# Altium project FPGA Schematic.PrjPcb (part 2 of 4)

## Sheet TPSM5D1806 Multi Phase.SchDoc
size A2; Date: Not shown in title block; ApprovedBy: Not shown in title block; CheckedBy: Not shown in title block; Author: Not shown in title block; CompanyName: Not shown in title block; Engineer: Not shown in title block; Organization: Not shown in title block; Address1: Not shown in title block; Address2: Not shown in title block; Address3: Not shown in title block; Address4: Not shown in title block; DocumentNumber: 16; Revision: Use project parameter SCH_Rev; SheetNumber: 16; SheetTotal: 17; PageSetup: Record=PageOptions¦CenterHorizontal=True¦CenterVertical=True¦PrintScale=1.00¦XCorrection=1.00¦YCorrection=1.00¦PrintKind=0¦BorderSize=5000000¦LeftOffset=0¦BottomOffset=0¦Orientation=2¦PaperLength=1000¦PaperWidth=1000¦Scale=100¦PaperSource=15¦PrintQuality=600¦MediaType=1¦DitherType=10¦PaperKind=Letter¦PrintScaleMode=1
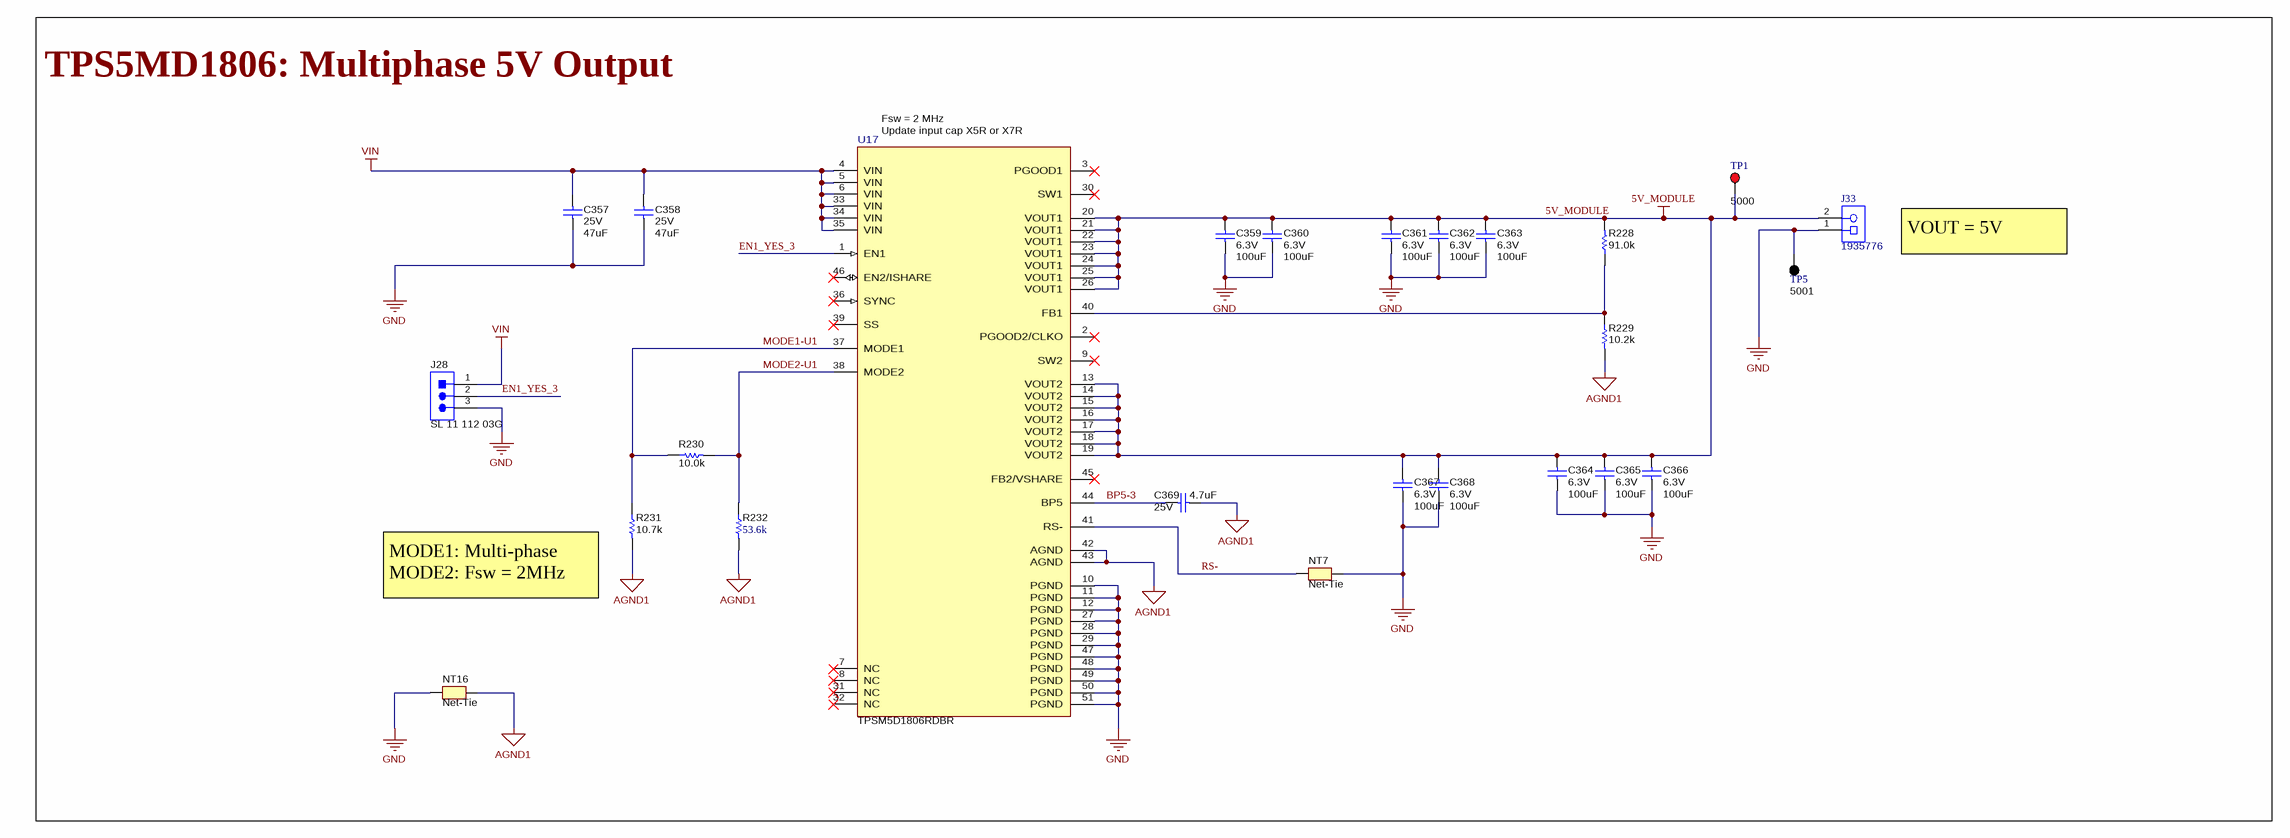
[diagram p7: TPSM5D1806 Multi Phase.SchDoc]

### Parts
C357  VDC_V: 25V  ValueDisplayed: 47uF  [1206_190L]  (hidden comment: CKG57NX5R1E476M500JH)
C358  VDC_V: 25V  ValueDisplayed: 47uF  [1206_190L]  (hidden comment: CKG57NX5R1E476M500JH)
C359  VDC_V: 6.3V  ValueDisplayed: 100uF  [0805L]  (hidden comment: GRM21BR60J107M)
C360  VDC_V: 6.3V  ValueDisplayed: 100uF  [0805L]  (hidden comment: GRM21BR60J107M)
C361  VDC_V: 6.3V  ValueDisplayed: 100uF  [0805L]  (hidden comment: GRM21BR60J107M)
C362  VDC_V: 6.3V  ValueDisplayed: 100uF  [0805L]  (hidden comment: GRM21BR60J107M)
C363  VDC_V: 6.3V  ValueDisplayed: 100uF  [0805L]  (hidden comment: GRM21BR60J107M)
C364  VDC_V: 6.3V  ValueDisplayed: 100uF  [0805L]  (hidden comment: GRM21BR60J107M)
C365  VDC_V: 6.3V  ValueDisplayed: 100uF  [0805L]  (hidden comment: GRM21BR60J107M)
C366  VDC_V: 6.3V  ValueDisplayed: 100uF  [0805L]  (hidden comment: GRM21BR60J107M)
C367  VDC_V: 6.3V  ValueDisplayed: 100uF  [0805L]  (hidden comment: GRM21BR60J107M)
C368  VDC_V: 6.3V  ValueDisplayed: 100uF  [0805L]  (hidden comment: GRM21BR60J107M)
C369  VDC_V: 25V  ValueDisplayed: 4.7uF  [0402]  (hidden comment: GRM155R61E475ME15)
J28  SL 11 112 03G  [Fischer_SL-11-112-03G]
J33  1935776  [Phoenix_1935776]
NT7  Net-Tie  [Net-Tie6milsWide_20milsLong]  (net tie, no BOM)
NT16  Net-Tie  [Net-Tie_10mil]  (net tie, no BOM)
R228  ValueDisplayed: 91.0k  [0201L]  (hidden comment: RC0201FR-0791KL)
R229  ValueDisplayed: 10.2k  [0201L]  (hidden comment: RC0201FR-0710K2L)
R230  ValueDisplayed: 10.0k  [0201L]  (hidden comment: RC0201FR-7D10KL)
R231  ValueDisplayed: 10.7k  [0201L]  (hidden comment: RC0201FR-0710K7L)
R232  ValueDisplayed: 53.6k  [0201L]  (hidden comment: RC0201FR-0753K6L)
TP1  5000  [Keystone5000]
TP5  5001  [Keystone5001]
U17  PartNumber: TPSM5D1806RDBR  [RDB0051A-MFG]  (hidden comment: TPSM5D1806RDB)

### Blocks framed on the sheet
TPS5MD1806: Multiphase 5V Output: C357-C369 J28 J33 NT7 NT16 R228-R232 TP1 TP5 U17

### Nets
5V_MODULE: C359.1 C360.1 C361.1 C362.1 C363.1 C364.1 C365.1 C366.1 C367.1 C368.1 J33.2 R228.2 TP1.1 U17.13(VOUT2) U17.14(VOUT2) U17.15(VOUT2) U17.16(VOUT2) U17.17(VOUT2) U17.18(VOUT2) U17.19(VOUT2) U17.20(VOUT1) U17.21(VOUT1) U17.22(VOUT1) U17.23(VOUT1) U17.24(VOUT1) U17.25(VOUT1) U17.26(VOUT1)
AGND1: C369.2 NT16.2 R229.2 R231.2 R232.2 U17.42(AGND) U17.43(AGND)
GND: C357.2 C358.2 C359.2 C360.2 C361.2 C362.2 C363.2 C364.2 C365.2 C366.2 C367.2 C368.2 J28.3 J33.1 NT7.2 NT16.1 TP5.1 U17.10(PGND) U17.11(PGND) U17.12(PGND) U17.27(PGND) U17.28(PGND) U17.29(PGND) U17.47(PGND) U17.48(PGND) U17.49(PGND) U17.50(PGND) U17.51(PGND)
VIN: C357.1 C358.1 J28.1 U17.4(VIN) U17.5(VIN) U17.6(VIN) U17.33(VIN) U17.34(VIN) U17.35(VIN)
BP5-3: C369.1 U17.44(BP5)
EN1_YES_3: J28.2 U17.1(EN1)
MODE1-U1: R230.1 R231.1 U17.37(MODE1)
MODE2-U1: R230.2 R232.1 U17.38(MODE2)
RS-: NT7.1 U17.41(RS-)
NetR228_1: R228.1 R229.1 U17.40(FB1)

Not connected (* = marked no-connect by the designer): U17 2(PGOOD2/CLKO)* 3(PGOOD1)* 7(NC)* 8(NC)* 9(SW2)* 30(SW1)* 31(NC)* 32(NC)* 36(SYNC)* 39(SS)* 45(FB2/VSHARE)* 46(EN2/ISHARE)*

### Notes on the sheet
- (near U17) Fsw = 2 MHz
  Update input cap X5R or X7R
- VOUT = 5V
- (near R231) MODE1: Multi-phase
  MODE2: Fsw = 2MHz

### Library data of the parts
C357 C358 = CMP-0008656-2: CAP, CERM, 47 uF, 25 V, +/- 20%, X5R, 1206_190; Manufacturer: TDK; PartNumber: C3216X5R1E476M160AC; TaMin_C: -55°C; Polarized: N; SizeAreaWB_mm2: 10.92; Value1: Unknown; U/M: EA; Value: 47uF; TaMax_C: 85°C; SizeZ_mm: 1.9; SizeX_mm: 3.2; SizeY_mm: 1.6; Cap_Case: 1206; SizeArea_mm2: 5.12; Cap_F: 47µF; AEC Category: Q200
C359-C368 = CMP-0008280-2: CAP, CERM, 100 uF, 6.3 V, +/- 20%, X5R, 0805; Manufacturer: MuRata; TaMin_C: -55°C; Polarized: N; SizeAreaWB_mm2: 6.75; Value1: Unknown; U/M: EA; Value: 100uF; TaMax_C: 85°C; SizeZ_mm: 1.45; SizeX_mm: 2; SizeY_mm: 1.25; Cap_Case: 0805; SizeArea_mm2: 2.5; Cap_F: 100µF; AEC Category: Q200
C369 = CMP-0006612-2: CAP, CERM, 4.7 uF, 25 V, +/- 20%, X5R, 0402; Manufacturer: MuRata; TaMin_C: -55°C; Polarized: N; SizeAreaWB_mm2: 3; Value1: Unknown; U/M: EA; Value: 4.7uF; TaMax_C: 85°C; SizeZ_mm: 0.6; SizeX_mm: 1; SizeY_mm: 0.5; Cap_F: 4.7µF; AEC Category: Q200
J28 = CMP-0075048-1: Header, 2.54mm, 3x1, Gold, TH; Manufacturer: Fischer Elektronik; CT: False; CNHeader: True
J33 = CMP-0055506-1: Terminal Block, 2x1, 5mm, Green, TH; Manufacturer: Phoenix Contact; Pitch_mm: 5; Gender: Female; Row_Count: 1; CNHeader: FALSE; Green_Lifecycle: Not Set; Green_REACh: Incomplete; CT: TRUE
NT7 NT16 = CMP-0078142-4: Single point connection between nets.
R228 = CMP-0027922-1: RES, 91.0 k, 1%, 0.05 W, 0201; Manufacturer: Yageo America; Power_W: 50mW; TempCo: 200 ppm/C; Value_Code: 91k0; U/M: EA; Value: 91.0k; Res_ohm: 91k; SizeX_mm: 0.6; SizeY_mm: 0.3; SizeZ_mm: 0.26; Value2: 0.05W; SizeArea_mm2: 0.18; AEC Qualified: N; VDC_V: 25V; AEC Category: Q200
R229 = CMP-0027301-2: RES, 10.2 k, 1%, 0.05 W, 0201; Manufacturer: Yageo America; Power_W: 50mW; TempCo: 200 ppm/C; Value_Code: 10k2; Value: 10.2k; EIA_Code: E96; SizeX_mm: 0.6; SizeY_mm: 0.3; SizeZ_mm: 0.26; Value2: 0.05W; SizeArea_mm2: 0.18; AEC Qualified: N; VDC_V: 25V; AEC Category: Q200; U/M: EA
R230 = CMP-0027945-1: RES, 10.0 k, 1%, 0.05 W, 0201; Manufacturer: Yageo America; Power_W: 50mW; TempCo: 200 ppm/C; Value_Code: 10k0; U/M: EA; Value: 10.0k; EIA_Code: E96; Res_ohm: 10k; SizeX_mm: 0.6; SizeY_mm: 0.3; SizeZ_mm: 0.26; Value2: 0.05W; SizeArea_mm2: 0.18; AEC Qualified: N; VDC_V: 25V; AEC Category: Q200
R231 = CMP-0027303-2: RES, 10.7 k, 1%, 0.05 W, 0201; Manufacturer: Yageo America; Power_W: 50mW; TempCo: 200 ppm/C; Value_Code: 10k7; U/M: EA; Value: 10.7k; EIA_Code: E96; SizeX_mm: 0.6; SizeY_mm: 0.3; SizeZ_mm: 0.26; Value2: 0.05W; SizeArea_mm2: 0.18; CompType: Resistor; AEC Qualified: N; VDC_V: 25V; AEC Category: Q200
R232 = CMP-0027766-1: RES, 53.6 k, 1%, 0.05 W, 0201; Manufacturer: Yageo America; Power_W: 50mW; TempCo: 200 ppm/C; Value_Code: 53k6; U/M: EA; Value: 53.6k; EIA_Code: E96; SizeX_mm: 0.6; SizeY_mm: 0.3; SizeZ_mm: 0.26; Value2: 0.05W; SizeArea_mm2: 0.18; AEC Qualified: N; VDC_V: 25V; AEC Category: Q200
TP1 = CMP-0055137-1: Test Point, Miniature, Red, TH; Manufacturer: Keystone; ContactFinish: Silver; CNHeader: FALSE; Green_Lifecycle: Active; Green_REACh: Passed; CT: TRUE
TP5 = CMP-0055138-1: Test Point, Miniature, Black, TH; Manufacturer: Keystone; ContactFinish: Silver; CNHeader: FALSE; Green_Lifecycle: Active; Green_REACh: Passed; CT: TRUE
U17 = CMP-0090775-3: 4.5-V to 18-V Input, Dual 6-A / Single 12-A Output Power Module with Current Sharing; Manufacturer: Texas Instruments; AEC Qualified: No; Switching Frequency: 500-1000-1500-2000kHz; Output Voltage: 0.5-5.5V; Output Type: AdjustableProgrammable; TJmax_C: +125°C; Min Supply Voltage: 4.5V; Max Supply Voltage: 18V; Number Of Outputs: 2; Nominal Supply Current: 2.5mA; SizeZ_mm: 1.9mm; Switching Topology: Buck; TaMin_C: -40°C; TaMax_C: +105°C; CompType: IC; AEC Category: Q200

## Sheet EVRHC008_  Filters.SchDoc
size 431 x 279 mm; Date: Not shown in title block; ApprovedBy: Not shown in title block; CheckedBy: Not shown in title block; Author: Not shown in title block; CompanyName: Not shown in title block; Engineer: Not shown in title block; Organization: Not shown in title block; Address1: Not shown in title block; Address2: Not shown in title block; Address3: Not shown in title block; Address4: Not shown in title block; DocumentNumber: 2; Revision: Use project parameter SCH_Rev; SheetNumber: 2; SheetTotal: 17; PageSetup: Record=PageOptions¦CenterHorizontal=True¦CenterVertical=True¦PrintScale=1.00¦XCorrection=1.00¦YCorrection=1.00¦PrintKind=0¦BorderSize=5000000¦LeftOffset=0¦BottomOffset=0¦Orientation=2¦PaperLength=1000¦PaperWidth=1000¦Scale=100¦PaperSource=15¦PrintQuality=600¦MediaType=1¦DitherType=10¦PaperKind=Letter¦PrintScaleMode=1
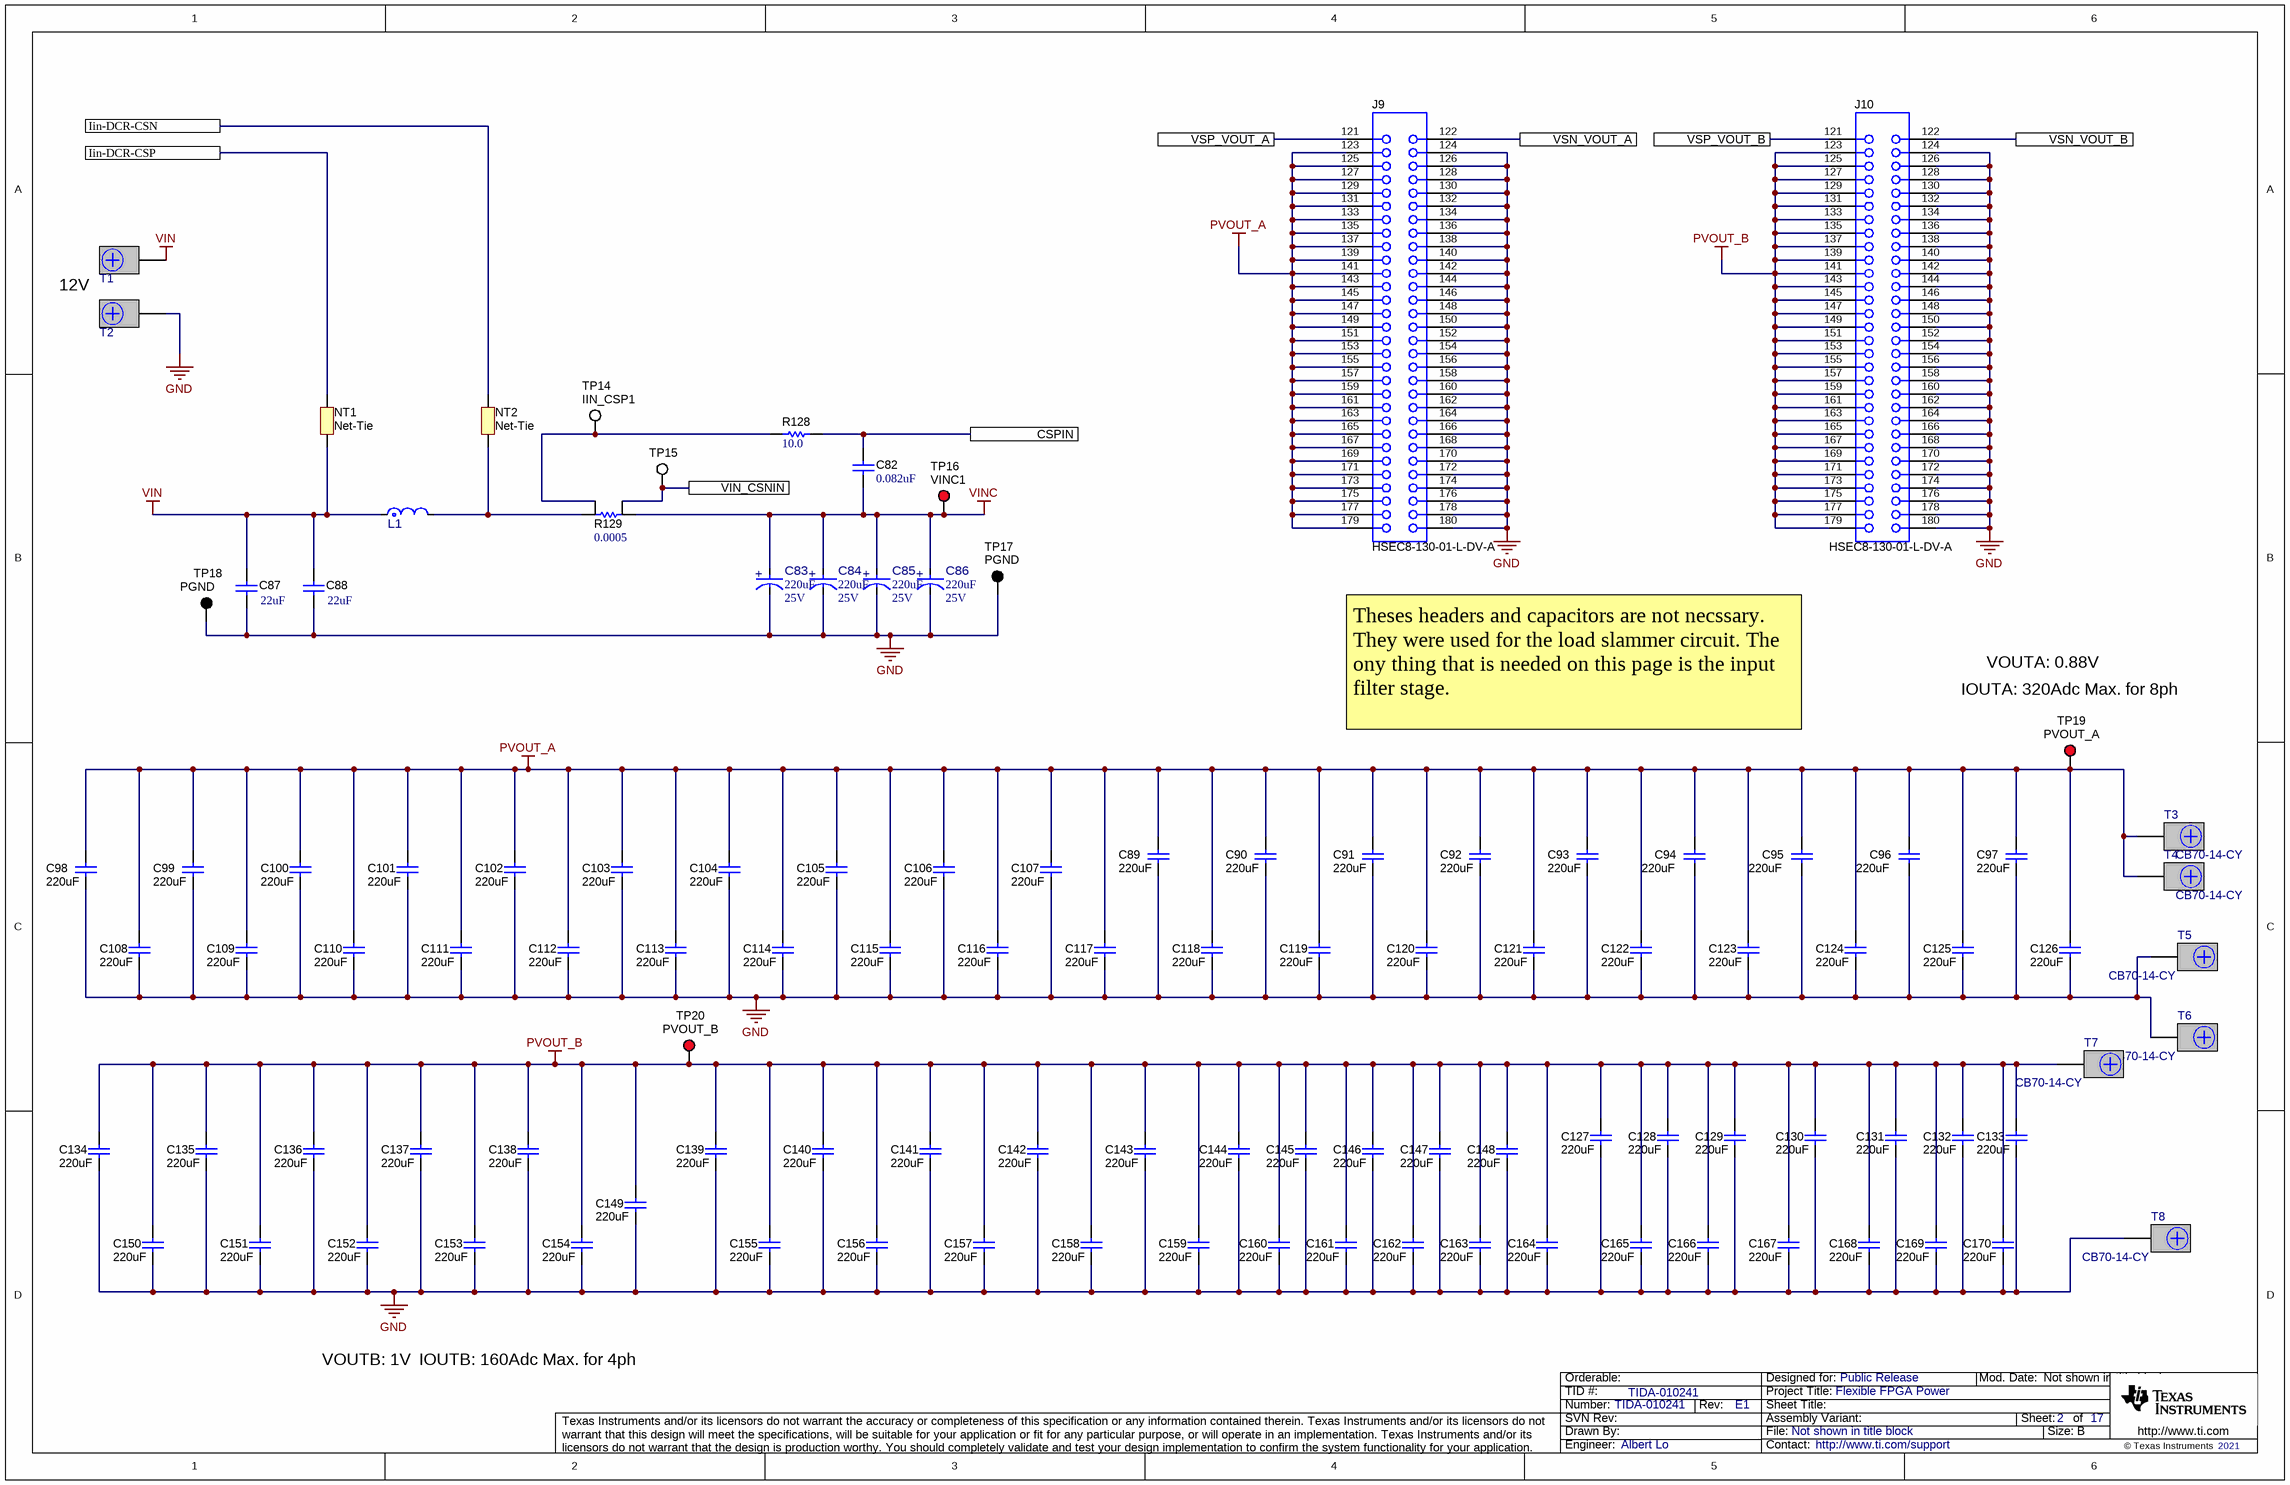
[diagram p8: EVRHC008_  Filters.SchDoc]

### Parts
C82  ValueDisplayed: 0.082uF  [0603S]  (hidden comment: 0603YC823KAT2A)
C83  ValueDisplayed: 220uF  VDC_V: 25V  [FP-TCN4227M025R0100_2924-MFG]  (hidden comment: TCN4227M025R0100)
C84  ValueDisplayed: 220uF  VDC_V: 25V  [FP-TCN4227M025R0100_2924-MFG]  (hidden comment: TCN4227M025R0100)
C85  ValueDisplayed: 220uF  VDC_V: 25V  [FP-TCN4227M025R0100_2924-MFG]  (hidden comment: TCN4227M025R0100)
C86  ValueDisplayed: 220uF  VDC_V: 25V  [FP-TCN4227M025R0100_2924-MFG]  (hidden comment: TCN4227M025R0100)
C87  ValueDisplayed: 22uF  [1206_180L]  (hidden comment: C3216X5R1V226M160AC)
C88  ValueDisplayed: 22uF  [1206_180L]  (hidden comment: C3216X5R1V226M160AC)
C89  ValueDisplayed: 220uF  [1206_190L]  (hidden comment: GRM31CR60G227ME11L)
C90  ValueDisplayed: 220uF  [1206_190L]  (hidden comment: GRM31CR60G227ME11L)
C91  ValueDisplayed: 220uF  [1206_190L]  (hidden comment: GRM31CR60G227ME11L)
C92  ValueDisplayed: 220uF  [1206_190L]  (hidden comment: GRM31CR60G227ME11L)
C93  ValueDisplayed: 220uF  [1206_190L]  (hidden comment: GRM31CR60G227ME11L)
C94  ValueDisplayed: 220uF  [1206_190L]  (hidden comment: GRM31CR60G227ME11L)
C95  ValueDisplayed: 220uF  [1206_190L]  (hidden comment: GRM31CR60G227ME11L)
C96  ValueDisplayed: 220uF  [1206_190L]  (hidden comment: GRM31CR60G227ME11L)
C97  ValueDisplayed: 220uF  [1206_190L]  (hidden comment: GRM31CR60G227ME11L)
C98  ValueDisplayed: 220uF  [1206_190L]  (hidden comment: GRM31CR60G227ME11L)
C99  ValueDisplayed: 220uF  [1206_190L]  (hidden comment: GRM31CR60G227ME11L)
C100  ValueDisplayed: 220uF  [1206_190L]  (hidden comment: GRM31CR60G227ME11L)
C101  ValueDisplayed: 220uF  [1206_190L]  (hidden comment: GRM31CR60G227ME11L)
C102  ValueDisplayed: 220uF  [1206_190L]  (hidden comment: GRM31CR60G227ME11L)
C103  ValueDisplayed: 220uF  [1206_190L]  (hidden comment: GRM31CR60G227ME11L)
C104  ValueDisplayed: 220uF  [1206_190L]  (hidden comment: GRM31CR60G227ME11L)
C105  ValueDisplayed: 220uF  [1206_190L]  (hidden comment: GRM31CR60G227ME11L)
C106  ValueDisplayed: 220uF  [1206_190L]  (hidden comment: GRM31CR60G227ME11L)
C107  ValueDisplayed: 220uF  [1206_190L]  (hidden comment: GRM31CR60G227ME11L)
C108  ValueDisplayed: 220uF  [1206_190L]  (hidden comment: GRM31CR60G227ME11L)
C109  ValueDisplayed: 220uF  [1206_190L]  (hidden comment: GRM31CR60G227ME11L)
C110  ValueDisplayed: 220uF  [1206_190L]  (hidden comment: GRM31CR60G227ME11L)
C111  ValueDisplayed: 220uF  [1206_190L]  (hidden comment: GRM31CR60G227ME11L)
C112  ValueDisplayed: 220uF  [1206_190L]  (hidden comment: GRM31CR60G227ME11L)
C113  ValueDisplayed: 220uF  [1206_190L]  (hidden comment: GRM31CR60G227ME11L)
C114  ValueDisplayed: 220uF  [1206_190L]  (hidden comment: GRM31CR60G227ME11L)
C115  ValueDisplayed: 220uF  [1206_190L]  (hidden comment: GRM31CR60G227ME11L)
C116  ValueDisplayed: 220uF  [1206_190L]  (hidden comment: GRM31CR60G227ME11L)
C117  ValueDisplayed: 220uF  [1206_190L]  (hidden comment: GRM31CR60G227ME11L)
C118  ValueDisplayed: 220uF  [1206_190L]  (hidden comment: GRM31CR60G227ME11L)
C119  ValueDisplayed: 220uF  [1206_190L]  (hidden comment: GRM31CR60G227ME11L)
C120  ValueDisplayed: 220uF  [1206_190L]  (hidden comment: GRM31CR60G227ME11L)
C121  ValueDisplayed: 220uF  [1206_190L]  (hidden comment: GRM31CR60G227ME11L)
C122  ValueDisplayed: 220uF  [1206_190L]  (hidden comment: GRM31CR60G227ME11L)
C123  ValueDisplayed: 220uF  [1206_190L]  (hidden comment: GRM31CR60G227ME11L)
C124  ValueDisplayed: 220uF  [1206_190L]  (hidden comment: GRM31CR60G227ME11L)
C125  ValueDisplayed: 220uF  [1206_190L]  (hidden comment: GRM31CR60G227ME11L)
C126  ValueDisplayed: 220uF  [1206_190L]  (hidden comment: GRM31CR60G227ME11L)
C127  ValueDisplayed: 220uF  [1206_190L]  (hidden comment: GRM31CR60G227ME11L)
C128  ValueDisplayed: 220uF  [1206_190L]  (hidden comment: GRM31CR60G227ME11L)
C129  ValueDisplayed: 220uF  [1206_190L]  (hidden comment: GRM31CR60G227ME11L)
C130  ValueDisplayed: 220uF  [1206_190L]  (hidden comment: GRM31CR60G227ME11L)
C131  ValueDisplayed: 220uF  [1206_190L]  (hidden comment: GRM31CR60G227ME11L)
C132  ValueDisplayed: 220uF  [1206_190L]  (hidden comment: GRM31CR60G227ME11L)
C133  ValueDisplayed: 220uF  [1206_190L]  (hidden comment: GRM31CR60G227ME11L)
C134  ValueDisplayed: 220uF  [1206_190L]  (hidden comment: GRM31CR60G227ME11L)
C135  ValueDisplayed: 220uF  [1206_190L]  (hidden comment: GRM31CR60G227ME11L)
C136  ValueDisplayed: 220uF  [1206_190L]  (hidden comment: GRM31CR60G227ME11L)
C137  ValueDisplayed: 220uF  [1206_190L]  (hidden comment: GRM31CR60G227ME11L)
C138  ValueDisplayed: 220uF  [1206_190L]  (hidden comment: GRM31CR60G227ME11L)
C139  ValueDisplayed: 220uF  [1206_190L]  (hidden comment: GRM31CR60G227ME11L)
C140  ValueDisplayed: 220uF  [1206_190L]  (hidden comment: GRM31CR60G227ME11L)
C141  ValueDisplayed: 220uF  [1206_190L]  (hidden comment: GRM31CR60G227ME11L)
C142  ValueDisplayed: 220uF  [1206_190L]  (hidden comment: GRM31CR60G227ME11L)
C143  ValueDisplayed: 220uF  [1206_190L]  (hidden comment: GRM31CR60G227ME11L)
C144  ValueDisplayed: 220uF  [1206_190L]  (hidden comment: GRM31CR60G227ME11L)
C145  ValueDisplayed: 220uF  [1206_190L]  (hidden comment: GRM31CR60G227ME11L)
C146  ValueDisplayed: 220uF  [1206_190L]  (hidden comment: GRM31CR60G227ME11L)
C147  ValueDisplayed: 220uF  [1206_190L]  (hidden comment: GRM31CR60G227ME11L)
C148  ValueDisplayed: 220uF  [1206_190L]  (hidden comment: GRM31CR60G227ME11L)
C149  ValueDisplayed: 220uF  [1206_190L]  (hidden comment: GRM31CR60G227ME11L)
C150  ValueDisplayed: 220uF  [1206_190L]  (hidden comment: GRM31CR60G227ME11L)
C151  ValueDisplayed: 220uF  [1206_190L]  (hidden comment: GRM31CR60G227ME11L)
C152  ValueDisplayed: 220uF  [1206_190L]  (hidden comment: GRM31CR60G227ME11L)
C153  ValueDisplayed: 220uF  [1206_190L]  (hidden comment: GRM31CR60G227ME11L)
C154  ValueDisplayed: 220uF  [1206_190L]  (hidden comment: GRM31CR60G227ME11L)
C155  ValueDisplayed: 220uF  [1206_190L]  (hidden comment: GRM31CR60G227ME11L)
C156  ValueDisplayed: 220uF  [1206_190L]  (hidden comment: GRM31CR60G227ME11L)
C157  ValueDisplayed: 220uF  [1206_190L]  (hidden comment: GRM31CR60G227ME11L)
C158  ValueDisplayed: 220uF  [1206_190L]  (hidden comment: GRM31CR60G227ME11L)
C159  ValueDisplayed: 220uF  [1206_190L]  (hidden comment: GRM31CR60G227ME11L)
C160  ValueDisplayed: 220uF  [1206_190L]  (hidden comment: GRM31CR60G227ME11L)
C161  ValueDisplayed: 220uF  [1206_190L]  (hidden comment: GRM31CR60G227ME11L)
C162  ValueDisplayed: 220uF  [1206_190L]  (hidden comment: GRM31CR60G227ME11L)
C163  ValueDisplayed: 220uF  [1206_190L]  (hidden comment: GRM31CR60G227ME11L)
C164  ValueDisplayed: 220uF  [1206_190L]  (hidden comment: GRM31CR60G227ME11L)
C165  ValueDisplayed: 220uF  [1206_190L]  (hidden comment: GRM31CR60G227ME11L)
C166  ValueDisplayed: 220uF  [1206_190L]  (hidden comment: GRM31CR60G227ME11L)
C167  ValueDisplayed: 220uF  [1206_190L]  (hidden comment: GRM31CR60G227ME11L)
C168  ValueDisplayed: 220uF  [1206_190L]  (hidden comment: GRM31CR60G227ME11L)
C169  ValueDisplayed: 220uF  [1206_190L]  (hidden comment: GRM31CR60G227ME11L)
C170  ValueDisplayed: 220uF  [1206_190L]  (hidden comment: GRM31CR60G227ME11L)
J9  HSEC8-130-01-L-DV-A  [controlCARD-180HSEC-60pinAddon]
J10  HSEC8-130-01-L-DV-A  [controlCARD-180HSEC-60pinAddon]
L1  PA4059.550HLT  [FP-PA4059.550HLT_SMT_IND_5MM5_5MM7-MFG]  (value not drawn)
NT1  Net-Tie  [Net-Tie_10mil]  (net tie, no BOM)
NT2  Net-Tie  [Net-Tie_10mil]  (net tie, no BOM)
R128  ValueDisplayed: 10.0  [0402S]  (hidden comment: CRCW040210R0FKED)
R129  ValueDisplayed: 0.0005  [RL1632L4]  (hidden comment: RL1632L4-0R5M-FNH)
T1  CB70-14-CY  [CB70-14-CY]  (value not drawn)
T2  CB70-14-CY  [CB70-14-CY]  (value not drawn)
T3  CB70-14-CY  [CB70-14-CY]
T4  CB70-14-CY  [CB70-14-CY]
T5  CB70-14-CY  [CB70-14-CY]
T6  CB70-14-CY  [CB70-14-CY]
T7  CB70-14-CY  [CB70-14-CY]
T8  CB70-14-CY  [CB70-14-CY]
TP14  IIN_CSP1  [Keystone5007]
TP15  5007  [Keystone5007]  (value not drawn)
TP16  VINC1  [Keystone5005]
TP17  PGND  [Keystone5006]
TP18  PGND  [Keystone5006]
TP19  PVOUT_A  [Keystone5005]
TP20  PVOUT_B  [Keystone5005]

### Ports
CSPIN, Iin-DCR-CSN, Iin-DCR-CSP, VIN_CSNIN, VSN_VOUT_A, VSN_VOUT_B, VSP_VOUT_A, VSP_VOUT_B

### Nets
GND: C83.1(CATHODE) C84.1(CATHODE) C85.1(CATHODE) C86.1(CATHODE) C87.2 C88.2 C89.2 C90.2 C91.2 C92.2 C93.2 C94.2 C95.2 C96.2 C97.2 C98.2 C99.2 C100.2 C101.2 C102.2 C103.2 C104.2 C105.2 C106.2 C107.2 C108.2 C109.2 C110.2 C111.2 C112.2 C113.2 C114.2 C115.2 C116.2 C117.2 C118.2 C119.2 C120.2 C121.2 C122.2 C123.2 C124.2 C125.2 C126.2 C127.2 C128.2 C129.2 C130.2 C131.2 C132.2 C133.2 C134.2 C135.2 C136.2 C137.2 C138.2 C139.2 C140.2 C141.2 C142.2 C143.2 C144.2 C145.2 C146.2 C147.2 C148.2 C149.2 C150.2 C151.2 C152.2 C153.2 C154.2 C155.2 C156.2 C157.2 C158.2 C159.2 C160.2 C161.2 C162.2 C163.2 C164.2 C165.2 C166.2 C167.2 C168.2 C169.2 C170.2 J9.124 J9.126 J9.128 J9.130 J9.132 J9.134 J9.136 J9.138 J9.140 J9.142 J9.144 J9.146 J9.148 J9.150 J9.152 J9.154 J9.156 J9.158 J9.160 J9.162 J9.164 J9.166 J9.168 J9.170 J9.172 J9.174 J9.176 J9.178 J9.180 J10.124 J10.126 J10.128 J10.130 J10.132 J10.134 J10.136 J10.138 J10.140 J10.142 J10.144 J10.146 J10.148 J10.150 J10.152 J10.154 J10.156 J10.158 J10.160 J10.162 J10.164 J10.166 J10.168 J10.170 J10.172 J10.174 J10.176 J10.178 J10.180 T2.1 T5.1 T6.1 T8.1 TP17.1 TP18.1
PVOUT_A: C89.1 C90.1 C91.1 C92.1 C93.1 C94.1 C95.1 C96.1 C97.1 C98.1 C99.1 C100.1 C101.1 C102.1 C103.1 C104.1 C105.1 C106.1 C107.1 C108.1 C109.1 C110.1 C111.1 C112.1 C113.1 C114.1 C115.1 C116.1 C117.1 C118.1 C119.1 C120.1 C121.1 C122.1 C123.1 C124.1 C125.1 C126.1 J9.123 J9.125 J9.127 J9.129 J9.131 J9.133 J9.135 J9.137 J9.139 J9.141 J9.143 J9.145 J9.147 J9.149 J9.151 J9.153 J9.155 J9.157 J9.159 J9.161 J9.163 J9.165 J9.167 J9.169 J9.171 J9.173 J9.175 J9.177 J9.179 T3.1 T4.1 TP19.1
PVOUT_B: C127.1 C128.1 C129.1 C130.1 C131.1 C132.1 C133.1 C134.1 C135.1 C136.1 C137.1 C138.1 C139.1 C140.1 C141.1 C142.1 C143.1 C144.1 C145.1 C146.1 C147.1 C148.1 C149.1 C150.1 C151.1 C152.1 C153.1 C154.1 C155.1 C156.1 C157.1 C158.1 C159.1 C160.1 C161.1 C162.1 C163.1 C164.1 C165.1 C166.1 C167.1 C168.1 C169.1 C170.1 J10.123 J10.125 J10.127 J10.129 J10.131 J10.133 J10.135 J10.137 J10.139 J10.141 J10.143 J10.145 J10.147 J10.149 J10.151 J10.153 J10.155 J10.157 J10.159 J10.161 J10.163 J10.165 J10.167 J10.169 J10.171 J10.173 J10.175 J10.177 J10.179 T7.1 TP20.1
VIN: C87.1 C88.1 L1.1 NT1.1 T1.1
VINC: C82.2 C83.2(ANODE) C84.2(ANODE) C85.2(ANODE) C86.2(ANODE) R129.2 TP16.1
VSN_VOUT_A: J9.122 ; port VSN_VOUT_A
VSN_VOUT_B: J10.122 ; port VSN_VOUT_B
VSP_VOUT_A: J9.121 ; port VSP_VOUT_A
VSP_VOUT_B: J10.121 ; port VSP_VOUT_B
NetC82_1: C82.1 R128.1 ; port CSPIN
NetL1_2: L1.2 NT2.1 R129.1
NetNT1_2: NT1.2 ; port Iin-DCR-CSP
NetNT2_2: NT2.2 ; port Iin-DCR-CSN
NetR38_1: R129.4 TP15.1 ; port VIN_CSNIN
NetR128_2: R128.2 R129.3 TP14.1

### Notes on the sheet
- 12V
- VOUTA: 0.88V
- IOUTA: 320Adc Max. for 8ph
- Theses headers and capacitors are not necssary. They were used for the load slammer circuit. The ony thing that is needed on this page is the input filter stage.
- VOUTB: 1V
- IOUTB: 160Adc Max. for 4ph

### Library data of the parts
C82 = CMP-0006810-4: CAP, CERM, 0.082 uF, 16 V, +/- 10%, X7R, 0603; Manufacturer: AVX; Polarized: N; U/M: EA; Cap_F: 82nF; ESR_ohm: 42m; Value1: 0.042 ohm; VDC_V: 16V; TaMin_C: -55°C; TaMax_C: 125°C; Cap_Case: 0603; SizeArea_mm2: 1.28; SizeAreaWB_mm2: 4.68; SizeX_mm: 1.6; SizeY_mm: 0.8; SizeZ_mm: 1; AEC Category: Q200
C83-C86 = CMP-0092821-1: 220µF Molded Tantalum Polymer Capacitor 25V 2924 (7361 Metric) 100mOhm @ 100kHz; Manufacturer: AVX; Life: 2000Hours; SizeZ_mm: 2mm; Leakage Current: 550uA; Dissipation Factor: 10%; Tolerance_%: 20%; IRMS_A: 1.38A; AEC Qualified: No; Esr: 0.1
C87 C88 = CMP-0008667-2: CAP, CERM, 22 uF, 35 V, +/- 20%, X5R, 1206; Manufacturer: TDK; TaMin_C: -55°C; ESR_ohm: 2.398m; Polarized: N; SizeAreaWB_mm2: 10.92; Value1: 0.002398 ohm; U/M: EA; Value: 22uF; TaMax_C: 85°C; SizeZ_mm: 1.8; SizeX_mm: 3.2; SizeY_mm: 1.6; Cap_Case: 1206_180; Value2: 35V; SizeArea_mm2: 5.12; Cap_F: 22µF; IRMS_A: 4.6851A; AEC Category: Q200
C89-C170 = CMP-0008932-2: CAP, CERM, 220 uF, 4 V, +/- 20%, X5R, 1206_190; Manufacturer: MuRata; Polarized: N; Value: 220uF; U/M: EA; Cap_F: 220µF; Value1: Unknown; VDC_V: 4V; TaMin_C: -55°C; TaMax_C: 85°C; Cap_Case: 1206; SizeArea_mm2: 5.12; SizeAreaWB_mm2: 10.92; SizeX_mm: 3.2; SizeY_mm: 1.6; SizeZ_mm: 1.9; AEC Category: Q200
J9 J10 = CMP-0003859-2: C2000 controlCARD-180HSEC (60-pin addon) connector, SMT; Manufacturer: Samtec; Note: The pin numbering does not match Samtec datasheet
L1 = CMP-0092884-1: Fixed Ind 55NH 35A 0.2 Mohm SMD; Manufacturer: Pulse; Isat: 61A; Tolerance_%: 20%; Test Frequency: 100kHz; DCR_ohm: 220µ; SizeZ_mm: 4.6mm; Shrouded: true; AEC Qualified: No
NT1 NT2 = CMP-0078142-4: Single point connection between nets.
R128 = CMP-0025963-3: RES, 10.0, 1%, 0.063 W, AEC-Q200 Grade 0, 0402; Manufacturer: Vishay-Dale; Value: 10.0; Res_ohm: 10; Value_Code: 10R0; Power_W: 63mW; Value2: 0.063W; VDC_V: 50V; TempCo: 100 ppm/C; SizeArea_mm2: 0.5; SizeX_mm: 1; SizeZ_mm: 0.6; EIA_Code: E96; AEC Category: Q200; AEC Qualified: Y; AEC Grade: 0
R129 = CMP-0015255-1: RES, 0.0005, 1%, 1 W, 1.5x3.15mm; Manufacturer: Cyntec; Power_W: 1W; TempCo: 700 ppm/C; SizeAreaWB_mm2: 10.375; Value_Code: L5000; U/M: EA; Value: 0.0005; Res_ohm: 500µ; SizeX_mm: 1.5; SizeY_mm: 3.15; SizeZ_mm: 1.13; SizeArea_mm2: 4.725; CompType: Resistor; AEC Qualified: N; AEC Category: Q200
T1-T8 = CMP-0055443-2: Terminal 90A Lug; Manufacturer: Panduit; CompType: Screw Terminal; ContactFinish: Copper; Voltage_V: 600V; Cert_CULUS: Y; Green_Lifecycle: Not Set; Green_REACh: Incomplete
TP14 TP15 = CMP-0055144-1: Test Point, Compact, White, TH; Manufacturer: Keystone; ContactFinish: Silver; CNHeader: FALSE; CT: TRUE; Green_Lifecycle: Active; Green_REACh: Passed
TP16 TP19 TP20 = CMP-0055142-1: Test Point, Compact, Red, TH; Manufacturer: Keystone; ContactFinish: Silver; CNHeader: FALSE; CT: TRUE; Green_Lifecycle: Active; Green_REACh: Passed
TP17 TP18 = CMP-0055143-1: Test Point, Compact, Black, TH; Manufacturer: Keystone; ContactFinish: Silver; CNHeader: FALSE; CT: TRUE; Green_Lifecycle: Active; Green_REACh: Passed

## Sheet EVRHC008_ CONTROLLER_6X6.SchDoc
size 431 x 279 mm; Date: Not shown in title block; ApprovedBy: Not shown in title block; CheckedBy: Not shown in title block; Author: Not shown in title block; CompanyName: Not shown in title block; Engineer: Not shown in title block; Organization: Not shown in title block; Address1: Not shown in title block; Address2: Not shown in title block; Address3: Not shown in title block; Address4: Not shown in title block; DocumentNumber: 3; Revision: Use project parameter SCH_Rev; SheetNumber: 3; SheetTotal: 17; PageSetup: Record=PageOptions¦CenterHorizontal=True¦CenterVertical=True¦PrintScale=1.00¦XCorrection=1.00¦YCorrection=1.00¦PrintKind=0¦BorderSize=5000000¦LeftOffset=0¦BottomOffset=0¦Orientation=2¦PaperLength=1000¦PaperWidth=1000¦Scale=100¦PaperSource=15¦PrintQuality=600¦MediaType=1¦DitherType=10¦PaperKind=Letter¦PrintScaleMode=1
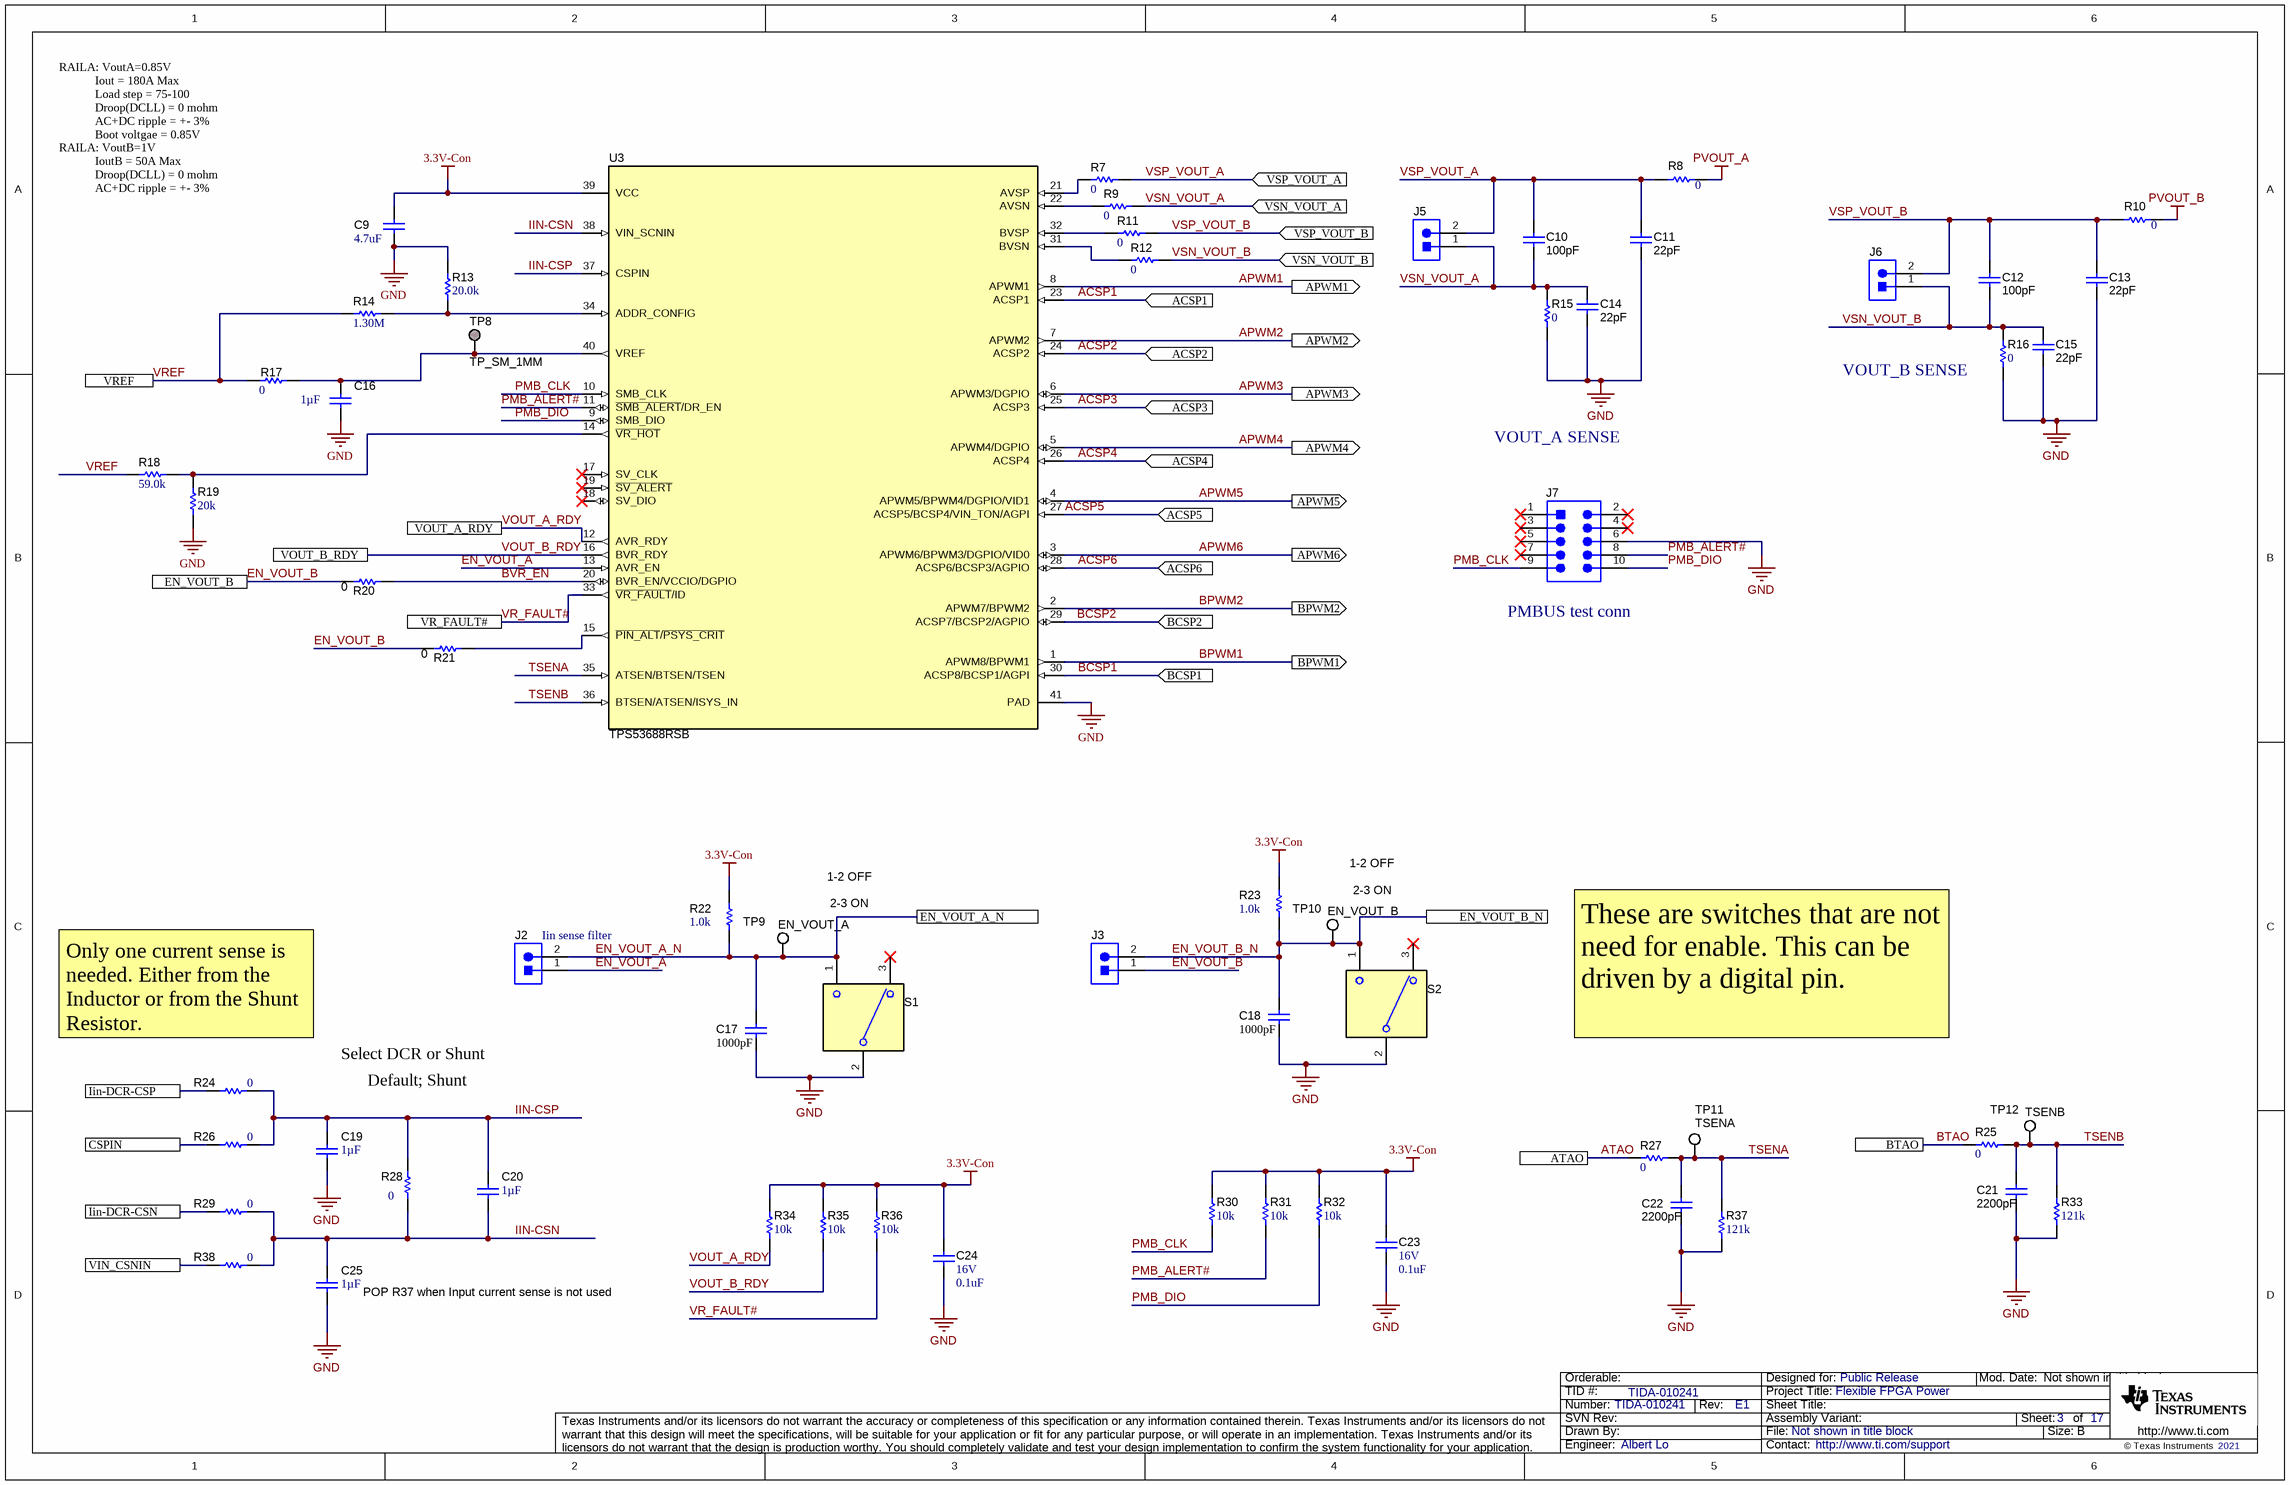
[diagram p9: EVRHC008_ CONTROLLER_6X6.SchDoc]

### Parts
C9  ValueDisplayed: 4.7uF  [0603S]  (hidden comment: C0603C475K8PACTU)
C10  ValueDisplayed: 100pF  [0402S]  (hidden comment: C0402C101J3GACTU)
C11  ValueDisplayed: 22pF  [0402S]  (hidden comment: GRM1555C1H220JA01D)
C12  ValueDisplayed: 100pF  [0402S]  (hidden comment: C0402C101J3GACTU)
C13  ValueDisplayed: 22pF  [0402S]  (hidden comment: GRM1555C1H220JA01D)
C14  ValueDisplayed: 22pF  [0402S]  (hidden comment: GRM1555C1H220JA01D)
C15  ValueDisplayed: 22pF  [0402S]  (hidden comment: GRM1555C1H220JA01D)
C16  Cap_F: 1µF  [0603S]  (hidden comment: GCM188R71C105KA64D)
C17  ValueDisplayed: 1000pF  [0402S]  (hidden comment: C0402C102K5RACTU)
C18  ValueDisplayed: 1000pF  [0402S]  (hidden comment: C0402C102K5RACTU)
C19  Cap_F: 1µF  [0603S]  (hidden comment: GCM188R71C105KA64D)
C20  Cap_F: 1µF  [0603S]  (hidden comment: GCM188R71C105KA64D)
C21  ValueDisplayed: 2200pF  [0402S]  (hidden comment: GRM155R71E222KA01D)
C22  ValueDisplayed: 2200pF  [0402S]  (hidden comment: GRM155R71E222KA01D)
C23  VDC_V: 16V  ValueDisplayed: 0.1uF  [0201]  (hidden comment: GRM033Z71C104KE14D)
C24  VDC_V: 16V  ValueDisplayed: 0.1uF  [0201]  (hidden comment: GRM033Z71C104KE14D)
C25  Cap_F: 1µF  [0603S]  (hidden comment: GCM188R71C105KA64D)
J2  TSW-102-07-G-S  [TSW-102-07-G-S]  (value not drawn)
J3  TSW-102-07-G-S  [TSW-102-07-G-S]  (value not drawn)
J5  TSW-102-07-G-S  [TSW-102-07-G-S]  (value not drawn)
J6  TSW-102-07-G-S  [TSW-102-07-G-S]  (value not drawn)
J7  5103308-1  [CONN_5103308-1]  (value not drawn)
R7  ValueDisplayed: 0  [0402S]  (hidden comment: CRCW04020000Z0ED)
R8  value 0  [0603S]  (hidden comment: CRCW06030000Z0EA)
R9  ValueDisplayed: 0  [0402S]  (hidden comment: CRCW04020000Z0ED)
R10  value 0  [0603S]  (hidden comment: CRCW06030000Z0EA)
R11  ValueDisplayed: 0  [0402S]  (hidden comment: CRCW04020000Z0ED)
R12  ValueDisplayed: 0  [0402S]  (hidden comment: CRCW04020000Z0ED)
R13  ValueDisplayed: 20.0k  [0603S]  (hidden comment: CRCW060320K0FKEA)
R14  ValueDisplayed: 1.30M  [0603S]  (hidden comment: CRCW06031M30FKEA)
R15  value 0  [0603S]  (hidden comment: CRCW06030000Z0EA)
R16  value 0  [0603S]  (hidden comment: CRCW06030000Z0EA)
R17  value 0  [0603S]  (hidden comment: CRCW06030000Z0EA)
R18  ValueDisplayed: 59.0k  [0402S]  (hidden comment: CRCW040259K0FKED)
R19  ValueDisplayed: 20k  [0402S]  (hidden comment: CRCW040220K0JNED)
R20  value 0  [0402S]  (hidden comment: CRCW04020000Z0ED)
R21  value 0  [0402S]  (hidden comment: CRCW04020000Z0ED)
R22  value 1.0k  [0603S]  (hidden comment: CRCW06031K00JNEA)
R23  value 1.0k  [0603S]  (hidden comment: CRCW06031K00JNEA)
R24  ValueDisplayed: 0  [0603S]  (hidden comment: CRCW06030000Z0EA)
R25  value 0  [0603S]  (hidden comment: CRCW06030000Z0EA)
R26  value 0  [0603S]  (hidden comment: CRCW06030000Z0EA)
R27  value 0  [0603S]  (hidden comment: CRCW06030000Z0EA)
R28  ValueDisplayed: 0  [0603S]  (hidden comment: CRCW06030000Z0EA)
R29  value 0  [0603S]  (hidden comment: CRCW06030000Z0EA)
R30  ValueDisplayed: 10k  [0201]  (hidden comment: RC0201JR-7D10KL)
R31  ValueDisplayed: 10k  [0201]  (hidden comment: RC0201JR-7D10KL)
R32  ValueDisplayed: 10k  [0201]  (hidden comment: RC0201JR-7D10KL)
R33  ValueDisplayed: 121k  [0603S]  (hidden comment: CRCW0603121KFKEA)
R34  ValueDisplayed: 10k  [0201]  (hidden comment: RC0201JR-7D10KL)
R35  ValueDisplayed: 10k  [0201]  (hidden comment: RC0201JR-7D10KL)
R36  ValueDisplayed: 10k  [0201]  (hidden comment: RC0201JR-7D10KL)
R37  ValueDisplayed: 121k  [0603S]  (hidden comment: CRCW0603121KFKEA)
R38  value 0  [0603S]  (hidden comment: CRCW06030000Z0EA)
S1  EG1218  [SW_EG1218]  (value not drawn)
S2  EG1218  [SW_EG1218]  (value not drawn)
TP8  TP_SM_1MM  [TP_SM_1MM]  (no BOM)
TP9  EN_VOUT_A  [Keystone5007]
TP10  EN_VOUT_B  [Keystone5007]
TP11  TSENA  [Keystone5007]
TP12  TSENB  [Keystone5007]
U3  TPS53688RSB  [RSB0040E]

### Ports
ACSP1 (in), ACSP2 (in), ACSP3 (in), ACSP4 (in), ACSP5 (in), ACSP6 (in), APWM1 (out), APWM2 (out), APWM3 (out), APWM4 (out), APWM5 (out), APWM6 (out), ATAO, BCSP1 (in), BCSP2 (in), BPWM1 (out), BPWM2 (out), BTAO, CSPIN, EN_VOUT_A_N, EN_VOUT_B, EN_VOUT_B_N, Iin-DCR-CSN, Iin-DCR-CSP, VIN_CSNIN, VOUT_A_RDY, VOUT_B_RDY, VR_FAULT#, VREF, VSN_VOUT_A (in), VSN_VOUT_B (in), VSP_VOUT_A (in), VSP_VOUT_B (in)

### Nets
3.3V-Con: C9.1 C23.1 C24.1 R22.2 R23.2 R30.2 R31.2 R32.2 R34.2 R35.2 R36.2 U3.39(VCC)
GND: C9.2 C11.2 C13.2 C14.2 C15.2 C16.2 C17.2 C18.2 C19.2 C21.2 C22.2 C23.2 C24.2 C25.2 J7.6 R13.1 R15.1 R16.1 R19.1 R33.1 R37.1 S1.2(COM) S2.2(COM) U3.41(PAD)
PVOUT_A: R8.2
PVOUT_B: R10.2
ACSP1: U3.23(ACSP1) ; port ACSP1
ACSP2: U3.24(ACSP2) ; port ACSP2
ACSP3: U3.25(ACSP3) ; port ACSP3
ACSP4: U3.26(ACSP4) ; port ACSP4
ACSP5: U3.27(ACSP5/BCSP4/VIN_TON/AGPI) ; port ACSP5
ACSP6: U3.28(ACSP6/BCSP3/AGPIO) ; port ACSP6
APWM1: U3.8(APWM1) ; port APWM1
APWM2: U3.7(APWM2) ; port APWM2
APWM3: U3.6(APWM3/DGPIO) ; port APWM3
APWM4: U3.5(APWM4/DGPIO) ; port APWM4
APWM5: U3.4(APWM5/BPWM4/DGPIO/VID1) ; port APWM5
APWM6: U3.3(APWM6/BPWM3/DGPIO/VID0) ; port APWM6
ATAO: R27.2 ; port ATAO
BCSP1: U3.30(ACSP8/BCSP1/AGPI) ; port BCSP1
BCSP2: U3.29(ACSP7/BCSP2/AGPIO) ; port BCSP2
BPWM1: U3.1(APWM8/BPWM1) ; port BPWM1
BPWM2: U3.2(APWM7/BPWM2) ; port BPWM2
BTAO: R25.2 ; port BTAO
BVR_EN: R20.2 U3.20(BVR_EN/VCCIO/DGPIO)
EN_VOUT_A: J2.1 U3.13(AVR_EN)
EN_VOUT_A_N: C17.1 J2.2 R22.1 S1.1 TP9.1 ; port EN_VOUT_A_N
EN_VOUT_B: J3.1 R20.1 R21.1 ; port EN_VOUT_B
EN_VOUT_B_N: C18.1 J3.2 R23.1 S2.1 TP10.1 ; port EN_VOUT_B_N
IIN-CSN: C20.2 C25.1 R28.1 R29.2 R38.2 U3.38(VIN_SCNIN)
IIN-CSP: C19.1 C20.1 R24.2 R26.2 R28.2 U3.37(CSPIN)
PMB_ALERT#: J7.8 R31.1 U3.11(~{SMB_ALERT}/DR_EN)
PMB_CLK: J7.9 R30.1 U3.10(SMB_CLK)
PMB_DIO: J7.10 R32.1 U3.9(SMB_DIO)
TSENA: C22.1 R27.1 R37.2 TP11.1 U3.35(ATSEN/BTSEN/TSEN)
TSENB: C21.1 R25.1 R33.2 TP12.1 U3.36(BTSEN/ATSEN/ISYS_IN)
VOUT_A_RDY: R34.1 U3.12(AVR_RDY) ; port VOUT_A_RDY
VOUT_B_RDY: R35.1 U3.16(BVR_RDY) ; port VOUT_B_RDY
VR_FAULT#: R36.1 U3.33(~{VR_FAULT}/ID) ; port VR_FAULT#
VREF: R14.1 R17.2 R18.1 ; port VREF
VSN_VOUT_A: C10.2 C14.1 J5.1 R9.1 R15.2 ; port VSN_VOUT_A
VSN_VOUT_B: C12.2 C15.1 J6.1 R12.1 R16.2 ; port VSN_VOUT_B
VSP_VOUT_A: C10.1 C11.1 J5.2 R7.1 R8.1 ; port VSP_VOUT_A
VSP_VOUT_B: C12.1 C13.1 J6.2 R10.1 R11.1 ; port VSP_VOUT_B
NetC16_1: C16.1 R17.1 TP8.1 U3.40(VREF)
NetC82_1: R26.1 ; port CSPIN
NetNT1_2: R24.1 ; port Iin-DCR-CSP
NetNT2_2: R29.1 ; port Iin-DCR-CSN
NetR7_2: R7.2 U3.21(AVSP)
NetR9_2: R9.2 U3.22(AVSN)
NetR11_2: R11.2 U3.32(BVSP)
NetR12_2: R12.2 U3.31(BVSN)
NetR13_2: R13.2 R14.2 U3.34(ADDR_CONFIG)
NetR18_2: R18.2 R19.2 U3.14(~{VR_HOT})
NetR21_2: R21.2 U3.15(~{PIN_ALT}/~{PSYS_CRIT})
NetR38_1: R38.1 ; port VIN_CSNIN

Not connected (* = marked no-connect by the designer): J7 1* 2* 3* 4* 5* 7*; S1 3*; S2 3*; U3 17(SV_CLK)* 18(SV_DIO)* 19(~{SV_ALERT})*

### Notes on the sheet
- RAILA: VoutA=0.85V
  Iout = 180A Max
  Load step = 75-100
  Droop(DCLL) = 0 mohm
  AC+DC ripple = +- 3%
  Boot voltgae = 0.85V
  RAILA: VoutB=1V
  IoutB = 50A Max
  Droop(DCLL) = 0 mohm
  AC+DC ripple = +- 3%
- VOUT_B SENSE
- VOUT_A SENSE
- (near J7) PMBUS test conn
- 1-2 OFF
- 2-3 ON
- (near TP10) 2-3 ON
- (near J2) Iin sense filter
- Only one current sense is needed. Either from the Inductor or from the Shunt Resistor.
- These are switches that are not need for enable. This can be driven by a digital pin.
- Select DCR or Shunt
- Default; Shunt
- (near C25) POP R37 when Input current sense is not used

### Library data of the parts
C9 = CMP-0006949-5: CAP, CERM, 4.7 uF, 10 V, +/- 10%, X5R, 0603; Manufacturer: Kemet; Polarized: N; Value: 4.7uF; U/M: EA; Cap_F: 4.7µF; ESR_ohm: 6m; Value1: 0.006 ohm; VDC_V: 10V; IRMS_A: 7.24A; TaMin_C: -55°C; TaMax_C: 85°C; Cap_Case: 0603; AEC Category: Q200; SizeArea_mm2: 1.28; SizeAreaWB_mm2: 4.68; SizeX_mm: 1.6; SizeY_mm: 0.8; SizeZ_mm: 1
C10 C12 = CMP-0006233-2: CAP, CERM, 100 pF, 25 V, +/- 5%, C0G/NP0, 0402; Manufacturer: Kemet; Polarized: N; Value: 100pF; U/M: EA; Value1: Unknown; VDC_V: 25V; TaMin_C: -55°C; TaMax_C: 125°C; Cap_Case: 0402; AEC Category: Q200; SizeArea_mm2: 0.5; SizeAreaWB_mm2: 3; SizeX_mm: 1; SizeZ_mm: 0.6
C11 C13-C15 = CMP-0006439-2: CAP, CERM, 22 pF, 50 V, +/- 5%, C0G/NP0, 0402; Manufacturer: MuRata; Polarized: N; Value: 22pF; U/M: EA; Value1: Unknown; VDC_V: 50V; TaMin_C: -55°C; TaMax_C: 125°C; Cap_Case: 0402; AEC Category: Q200; SizeArea_mm2: 0.5; SizeAreaWB_mm2: 3; SizeX_mm: 1; SizeZ_mm: 0.6
C16 C19 C20 C25 = CMP-0007136-5: CAP, CERM, 1 uF, 16 V, +/- 10%, X7R, AEC-Q200 Grade 1, 0603; Manufacturer: MuRata; TaMin_C: -55°C; Polarized: N; SizeAreaWB_mm2: 4.68; Value1: Unknown; U/M: EA; Value: 1uF; TaMax_C: 125°C; SizeZ_mm: 1; SizeX_mm: 1.6; SizeY_mm: 0.8; Cap_Case: 0603; Value2: 16V; SizeArea_mm2: 1.28; AEC Qualified: Y; AEC Category: Q200
C17 C18 = CMP-0006235-2: CAP, CERM, 1000 pF, 50 V, +/- 10%, X7R, 0402; Manufacturer: Kemet; TaMin_C: -55°C; Polarized: N; SizeAreaWB_mm2: 3; Value1: Unknown; U/M: EA; Value: 1000pF; TaMax_C: 125°C; SizeZ_mm: 0.6; SizeX_mm: 1; SizeY_mm: 0.5; Cap_Case: 0402; Value2: 50V; Cap_F: 1nF; AEC Category: Q200
C21 C22 = CMP-0006663-2: CAP, CERM, 2200 pF, 25 V, +/- 10%, X7R, 0402; Manufacturer: MuRata; TaMin_C: -55°C; Polarized: N; SizeAreaWB_mm2: 3; Value1: Unknown; U/M: EA; Value: 2200pF; TaMax_C: 125°C; SizeZ_mm: 0.6; SizeX_mm: 1; SizeY_mm: 0.5; Cap_Case: 0402; Value2: 25V; Cap_F: 2.2nF; AEC Category: Q200
C23 C24 = CMP-0064970-1: CAP, CERM, 0.1 uF, 16 V,+/- 10%, X7R, 0201; Manufacturer: MuRata; TaMin_C: -55°C; Polarized: N; SizeAreaWB_mm2: 2.08; Value1: Unknown; U/M: EA; Value: 0.1uF; TaMax_C: 125°C; SizeZ_mm: 0.26; SizeX_mm: 0.6; SizeY_mm: 0.3; SizeArea_mm2: 0.18; Cap_F: 100nF; AEC Category: Q200
J2 J3 J5 J6 = CMP-0075405-3: Header, 100mil, 2x1, Gold, TH; Manufacturer: Samtec; Pitch_mm: 2.54; Gender: Male; Shrouded: N; Row_Count: 1; Current_A: 6.3A; Voltage_V: 550V; Cert_CSA: Y; Green_Lifecycle: Active; Green_REACh: Passed
J7 = CMP-0054834-2: Header (shrouded), 100mil, 5x2, Gold, TH; Manufacturer: TE Connectivity; Green_Lifecycle: Active; Green_REACh: Passed
R7 R9 R11 R12 = CMP-0026822-3: RES, 0, 5%, 0.063 W, AEC-Q200 Grade 0, 0402; Manufacturer: Vishay-Dale; Value: 0; Value_Code: 0000; Power_W: 63mW; Value2: 0.063W; VDC_V: 50V; TempCo: 200 ppm/C; EIA_Code: E24; SizeArea_mm2: 0.5; SizeX_mm: 1; SizeZ_mm: 0.6; AEC Category: Q200; AEC Qualified: Y
R8 R10 R15-R17 R25-R27 R29 R38 = CMP-0025697-4: RES, 0, 5%, 0.1 W, AEC-Q200 Grade 0, 0603; Manufacturer: Vishay-Dale; Value_Code: 0000; Power_W: 100mW; Value2: 0.1W; VDC_V: 75V; TempCo: 200 ppm/C; EIA_Code: E24; AEC Category: Q200; AEC Qualified: Y; SizeArea_mm2: 1.28; SizeX_mm: 1.6; SizeY_mm: 0.8; SizeZ_mm: 1
R13 = CMP-0022204-4: RES, 20.0 k, 1%, 0.1 W, AEC-Q200 Grade 0, 0603; Manufacturer: Vishay-Dale; Power_W: 100mW; TempCo: 100 ppm/C; Value_Code: 20k0; Value: 20.0k; EIA_Code: E96; Res_ohm: 20k; SizeX_mm: 1.6; SizeY_mm: 0.8; SizeZ_mm: 1; Value2: 0.1W; SizeArea_mm2: 1.28; AEC Qualified: Y; VDC_V: 75V; AEC Category: Q200; AEC Grade: 0
R14 = CMP-0022150-4: RES, 1.30 M, 1%, 0.1 W, AEC-Q200 Grade 0, 0603; Manufacturer: Vishay-Dale; Power_W: 100mW; TempCo: 100 ppm/C; Value_Code: 1M30; Value: 1.30Meg; EIA_Code: E96; Res_ohm: 1.3M; SizeX_mm: 1.6; SizeY_mm: 0.8; SizeZ_mm: 1; Value2: 0.1W; SizeArea_mm2: 1.28; AEC Qualified: Y; VDC_V: 75V; AEC Category: Q200; AEC Grade: 0
R18 = CMP-0026461-2: RES, 59.0 k, 1%, 0.063 W, AEC-Q200 Grade 0, 0402; Manufacturer: Vishay-Dale; Power_W: 63mW; TempCo: 100 ppm/C; Value_Code: 59k0; Value: 59.0k; EIA_Code: E96; Res_ohm: 59k; SizeX_mm: 1; SizeY_mm: 0.5; SizeZ_mm: 0.6; Value2: 0.063W; AEC Qualified: Y; VDC_V: 50V; AEC Category: Q200; AEC Grade: 0
R19 = CMP-0026875-3: RES, 20 k, 5%, 0.063 W, AEC-Q200 Grade 0, 0402; Manufacturer: Vishay-Dale; Power_W: 63mW; TempCo: 200 ppm/C; Value_Code: 20k0; Value: 20k; EIA_Code: E24; SizeX_mm: 1; SizeY_mm: 0.5; SizeZ_mm: 0.6; Value2: 0.063W; AEC Qualified: Y; VDC_V: 50V; AEC Category: Q200; AEC Grade: 0
R20 R21 = CMP-0026822-3: RES, 0, 5%, 0.063 W, AEC-Q200 Grade 0, 0402; Manufacturer: Vishay-Dale; Value_Code: 0000; Power_W: 63mW; Value2: 0.063W; VDC_V: 50V; TempCo: 200 ppm/C; EIA_Code: E24; AEC Category: Q200; AEC Qualified: Y; SizeArea_mm2: 0.5; SizeX_mm: 1; SizeZ_mm: 0.6
R22 R23 = CMP-0025729-4: RES, 1.0 k, 5%, 0.1 W, AEC-Q200 Grade 0, 0603; Manufacturer: Vishay-Dale; Res_ohm: 1k; Value_Code: 1k00; Power_W: 100mW; Value2: 0.1W; VDC_V: 75V; TempCo: 200 ppm/C; EIA_Code: E24; AEC Category: Q200; AEC Grade: 0; AEC Qualified: Y; SizeArea_mm2: 1.28; SizeX_mm: 1.6; SizeY_mm: 0.8; SizeZ_mm: 1
R24 R28 = CMP-0025697-4: RES, 0, 5%, 0.1 W, AEC-Q200 Grade 0, 0603; Manufacturer: Vishay-Dale; Value: 0; Value_Code: 0000; Power_W: 100mW; Value2: 0.1W; VDC_V: 75V; TempCo: 200 ppm/C; EIA_Code: E24; AEC Category: Q200; AEC Qualified: Y; SizeArea_mm2: 1.28; SizeX_mm: 1.6; SizeY_mm: 0.8; SizeZ_mm: 1
R30-R32 R34-R36 = CMP-0027186-1: RES, 10 k, 5%, 0.05 W, 0201; Manufacturer: Yageo America; Power_W: 50mW; TempCo: 200 ppm/C; Value_Code: 10k0; U/M: EA; Value: 10k; EIA_Code: E24; SizeX_mm: 0.6; SizeY_mm: 0.3; SizeZ_mm: 0.26; Value2: 0.05W; SizeArea_mm2: 0.18; AEC Qualified: N; VDC_V: 25V; AEC Category: Q200
R33 R37 = CMP-0022024-4: RES, 121 k, 1%, 0.1 W, AEC-Q200 Grade 0, 0603; Manufacturer: Vishay-Dale; Value: 121k; Power_W: 100mW; Value2: 0.1W; VDC_V: 75V; TempCo: 100 ppm/C; EIA_Code: E96; AEC Category: Q200; AEC Grade: 0; AEC Qualified: Y; SizeArea_mm2: 1.28; SizeX_mm: 1.6; SizeY_mm: 0.8; SizeZ_mm: 1
S1 S2 = CMP-0002206-2: Switch, SPDT, Slide, On-On, 2 Pos, TH; Manufacturer: E-Switch; VDC_V: 30V; PositionCount: 2; CurrentRating_mA: 200A
TP8 = CMP-0003825-1: 1mm Test Point, SMT; Manufacturer: Any
TP9-TP12 = CMP-0055144-1: as TP14 on sheet EVRHC008_  Filters
U3 = CMP-0079528-1: TPS53688RSB, RSB0040E (WQFN-40); Manufacturer: Texas Instruments; SizeAreaWB_mm2: 49; SizeArea_mm2: 25; AEC Qualified: N; AEC Category: Q200; SizeZ_mm: 0.8; SizeY_mm: 5; CompType: IC; Comments: Customer Supplied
